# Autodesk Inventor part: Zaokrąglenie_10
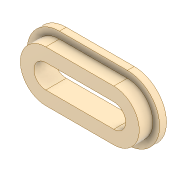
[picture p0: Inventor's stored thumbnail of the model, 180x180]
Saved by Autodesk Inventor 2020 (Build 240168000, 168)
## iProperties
Manager: www.cadconsulting.pl
Company: Fabian Stasiak CAD Consulting
Created: 2019-05
Part Number: Zaokrąglenie_10
Material: Polietylen o dużej gęstości
Document SubType Name: Modeling
Designer: F.Stasiak
Density: 0.952 g/cm^3
Appearance: Gładki — w kolorze złamanej bieli
Author: F.Stasiak
Subject: Zbiór ćwiczeń. Autodesk Inventor 2020. Kurs podstawowy
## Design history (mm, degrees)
sketch "Szkic1"
  geometry: L1 (-100, 0)-(100, 0); L2 (-100, -75)-(100, -75); L3 (100, 75)-(-100, 75); L4 (100, 35)-(-100, 35); L5 (-100, -35)-(100, -35); A1 r 75 centre (-100, 0) between (-100, 75) and (-100, -75); A2 r 75 centre (100, 0) between (100, -75) and (100, 75); A3 r 35 centre (-100, 0) between (-100, 35) and (-100, -35); A4 r 35 centre (100, 0) between (100, -35) and (100, 35); 1 further point
  constraints: 12 end point, 8 point on circle, 4 centre point, 4 tangent, 2 parallel, 1 horizontal, 1 midpoint, 3 other
  dimensions: "d0" = 100 distance of point (0, 0) L1.end; "d1" = 150 diameter of A2; "d2" = 40 radial gap between concentric circles of A2 A4
extrude "Wyciągnięcie proste1" new body sketch "Szkic1" distance "d3" = 40; taper "d4" = 0 deg; dims "d11" = 20, "d12" = 0
sketch "Szkic2"
  geometry: L1 (-100, -75)-(100, -75) reference; L2 (100, 75)-(-100, 75) reference; L3 (-100, -95)-(100, -95); L4 (100, 95)-(-100, 95); A1 r 75 centre (100, 0) between (100, -75) and (100, 75) reference; A2 r 75 centre (-100, 0) between (-100, 75) and (-100, -75) reference; A3 r 95 centre (100, 0) between (100, -95) and (100, 95); A4 r 95 centre (-100, 0) between (-100, 95) and (-100, -95); 1 further point
  constraints: 4 end point, 4 point on circle, 2 centre point, 3 other
  dimensions: "d10" = 20 distance between parallel lines of L4 L2
extrude "Wyciągnięcie proste2" join sketch "Szkic2" distance "d6" = 20; taper "d7" = 0 deg
node "Bryła1"
